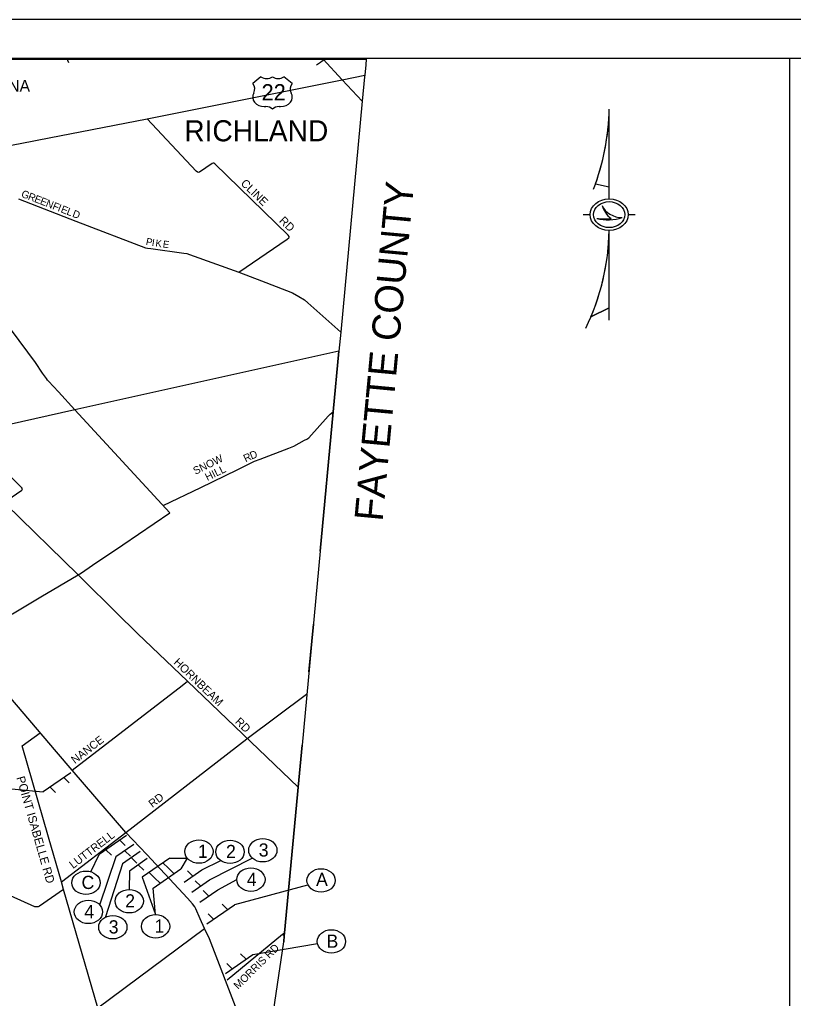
# Model space of a CAD drawing. Extents: x 0 to 784, y 0 to 440.
# Drawn here: x 266.5 to 466.8, y 186.8 to 440 of the extents above; entities that cross this region are included whole.
import ezdxf

# ---------------------------------------------------------------- set-up
doc = ezdxf.new("R2010")
doc.units = 0
for name, color, linetype in [('Default', 7, 'Continuous'), ('SH_Border', 7, 'Continuous'), ('SH_Cut_Line', 7, 'Continuous'), ('SH_Data', 7, 'Continuous'), ('SH_Text', 7, 'Continuous')]:
    doc.layers.add(name, color=color, linetype=linetype)

msp = doc.modelspace()

# ---------------------------------------------------------------- linework, layer by layer
at = {"layer": 'Default'}
for p, q in [((328.98, 425.22), (326.86, 423.46)), ((337.04, 423.46), (334.92, 425.22)), ((329.83, 417.48), (330.25, 417.48)), ((333.65, 417.48), (334.07, 417.48)), ((279.74, 245.14), (272.6, 240.17)), ((279.37, 242.5), (277.96, 243.9)), ((257.96, 241.64), (272.6, 240.17)), ((275.8, 240.02), (274.39, 241.41)), ((276.17, 242.65), (276.17, 242.65)), ((294.2, 228.93), (287.06, 223.96)), ((290.63, 226.45), (290.63, 226.45)), ((296.07, 226.57), (291.45, 223.36)), ((293.83, 226.29), (292.42, 227.69)), ((284.97, 219.55), (287.06, 223.96)), ((290.25, 223.81), (288.84, 225.2)), ((297.75, 224.77), (293.13, 221.56)), ((293.76, 224.97), (295.17, 223.57)), ((299.55, 222.94), (294.92, 219.72)), ((295.44, 223.17), (296.85, 221.77)), ((305.4, 223.05), (298.25, 218.09)), ((297.23, 221.33), (298.64, 219.94)), ((301.82, 220.57), (301.82, 220.57)), ((305.02, 220.42), (303.61, 221.81)), ((305.02, 220.43), (306.43, 219.04)), ((301.45, 217.94), (300.04, 219.33)), ((301.07, 215.31), (308.22, 220.28)), ((301.45, 217.95), (302.86, 216.55)), ((304.64, 217.8), (304.64, 217.8)), ((309.06, 216.8), (313.69, 220.01)), ((311.38, 218.4), (309.97, 219.8)), ((311.06, 214.22), (315.69, 217.44)), ((313.38, 215.83), (311.97, 217.22)), ((341.06, 216.06), (322.09, 210.99)), ((313.16, 211.65), (317.78, 214.86)), ((315.47, 213.26), (314.06, 214.65)), ((314.95, 206.03), (322.09, 210.99)), ((318.9, 211.15), (320.31, 209.75)), ((315.32, 208.66), (316.73, 207.27)), ((318.52, 208.51), (318.52, 208.51)), ((319.76, 193.2), (326.91, 198.16)), ((323.71, 198.31), (325.12, 196.92)), ((320.14, 195.83), (321.55, 194.44)), ((323.33, 195.68), (323.33, 195.68))]:
    msp.add_line(p, q, dxfattribs=at)
for points in [[(30.04, 429.76), (356.24, 429.76)], [(30.04, 429.76), (356.24, 429.76)], [(30.04, 429.76), (356.24, 429.76)], [(278.8, 429.76), (278.88, 429.49), (279.18, 428.86)], [(345.53, 429.76), (345.29, 429.54), (344.83, 429.21), (344.35, 428.89), (343.86, 428.58), (343.37, 428.24)], [(356.24, 429.76), (356.09, 428.25), (355.84, 425.6), (355.81, 425.19), (355.22, 418.92), (349.62, 359.12), (349.16, 354.22), (347.69, 338.55), (344.32, 302.45)], [(356.24, 429.76), (356.09, 428.25), (355.84, 425.6), (355.81, 425.19), (355.22, 418.92), (349.62, 359.12), (349.16, 354.22), (347.69, 338.55), (344.32, 302.45)], [(356.24, 429.76), (356.09, 428.25), (355.84, 425.6), (355.81, 425.19), (355.22, 418.92), (349.62, 359.12), (349.16, 354.22), (347.69, 338.55), (344.32, 302.45)], [(350.04, 424.44), (345.04, 429.76)], [(276.83, 409.9), (299.52, 414.29), (350.04, 424.44), (355.84, 425.6)], [(355.22, 418.92), (350.04, 424.44)], [(323.28, 374.64), (335.76, 383.21), (336.21, 383.54), (336.28, 383.74), (336.25, 383.91), (336.04, 384.24), (317.05, 402.68), (316.8, 402.87), (316.65, 402.88), (316.32, 402.79), (313.05, 400.56), (312.77, 400.46), (312.58, 400.49), (312.24, 400.74), (299.52, 414.29)], [(253.38, 405.36), (263.85, 407.39), (266.62, 407.92), (266.62, 407.92)], [(266.62, 407.92), (274.56, 409.46), (276.83, 409.9)], [(266.24, 393.59), (281.02, 387.86), (299.06, 380.98), (299.61, 380.85), (300.45, 380.74), (308.98, 379.61), (309.76, 379.47), (310.48, 379.21), (323.28, 374.64), (329.13, 372.44), (335.56, 369.94), (337.17, 369.28), (338.76, 368.39), (340.24, 367.53), (341.15, 366.72), (349.62, 359.12)], [(305.41, 312.35), (280.81, 339.02), (276.57, 343.66), (275.24, 345.07), (274.02, 346.43), (273.72, 346.74), (273.43, 347.14), (272.46, 348.48), (270.65, 351.32), (264.44, 359.64), (261.54, 363.43), (260.73, 364.63), (260.5, 365.11), (260.32, 365.8), (258.12, 377.41), (257.92, 377.84), (257.79, 378.04), (252.84, 382.75), (249.44, 385.84)], [(276.05, 250.6), (251.83, 278.94), (240.55, 292.26), (235.97, 297.77), (222.12, 314.36), (221.59, 314.93), (219.74, 316.8), (212.53, 323.9), (207.71, 328.65), (203.58, 332.82), (194.21, 342.12), (187.04, 349.36), (186.53, 349.9), (186.16, 350.28), (185.74, 350.86), (179.65, 358.52), (171.36, 368.89), (165.56, 376.17)], [(344.32, 302.45), (347.69, 338.55), (349.16, 354.22), (280.81, 339.02), (273.89, 337.48)], [(273.89, 337.48), (253.08, 332.85), (250.21, 332.22)], [(303.66, 314.26), (313.38, 318.97), (322.79, 323.53), (326.63, 325.4), (327.27, 325.72), (328.78, 326.29), (336.19, 329.08), (337.5, 329.67), (340.25, 331.16), (340.86, 331.41), (341.37, 331.79), (346.34, 337.36), (346.88, 337.88), (347.69, 338.55)], [(281.63, 296.37), (262.9, 314.64), (262.53, 314.98), (262.52, 315.04), (262.55, 315.12), (263.17, 315.58), (267.05, 318.28), (267.18, 318.42), (267.26, 318.63), (267.08, 318.87), (253.59, 332.34)], [(251.83, 278.94), (264.64, 286.29), (271.97, 290.62), (281.63, 296.37), (282.5, 296.91), (285.38, 298.87), (293.21, 304.09), (305.41, 312.35)], [(344.32, 302.45), (339.63, 252.31)], [(282.59, 295.42), (281.63, 296.37)], [(291.5, 286.63), (282.59, 295.42)], [(338.61, 241.45), (309.98, 268.81), (297.01, 281.21), (291.5, 286.63)], [(341.4, 271.25), (342.55, 283.57)], [(341.4, 271.25), (342.55, 283.57)], [(342.55, 283.57), (341.4, 271.25)], [(342.55, 283.57), (341.4, 271.25)], [(308.62, 267.76), (309.98, 268.81)], [(280.12, 245.85), (308.62, 267.76)], [(325.44, 254.01), (340.73, 265.44)], [(277.31, 216.93), (293.97, 229.72), (325.34, 253.93)], [(277.84, 214.9), (277.31, 216.93), (273.94, 228.48), (267.18, 252.09)], [(334.86, 201.37), (335, 202.95), (335.08, 203.76), (338.43, 239.52), (338.61, 241.45), (339.63, 252.31)], [(334.86, 201.37), (335, 202.95), (335.08, 203.76), (338.43, 239.52), (338.61, 241.45), (339.63, 252.31)], [(339.63, 252.31), (338.61, 241.45), (338.43, 239.52), (335.08, 203.76), (335, 202.95), (334.86, 201.37)], [(339.63, 252.31), (338.61, 241.45), (338.43, 239.52), (335.08, 203.76), (335, 202.95), (334.86, 201.37)], [(339.63, 252.31), (338.61, 241.45), (338.43, 239.52), (335.08, 203.76), (335, 202.95), (334.86, 201.37)], [(323.21, 182.43), (315.65, 202.22), (314.37, 204.87), (313.25, 207.38), (312.12, 209.93), (311.85, 210.45), (311.28, 211.22), (309.95, 212.69), (299.4, 224.01), (293.97, 229.72), (280.12, 245.85), (276.05, 250.6)], [(286.74, 184.37), (277.84, 214.9), (271.69, 210.64), (271.3, 210.44), (270.93, 210.44), (270.45, 210.49), (245.32, 221.77), (245.17, 221.81)], [(286.74, 184.37), (314.37, 204.87)], [(320.24, 191.56), (334.59, 203.36), (335.08, 203.76)], [(334.59, 203.36), (335, 202.95)], [(328.56, 159.01), (334.86, 201.37)]]:
    msp.add_lwpolyline(points, dxfattribs=at)
msp.add_lwpolyline([(31.33, 429.99), (465.77, 429.99), (465.77, 10.05), (31.33, 10.05)], close=True, dxfattribs=at)
for centre, major_axis, start_param, end_param in [((324.42, 422.05), (2.97, 0), 5.838949, 6.894067), ((330.47, 426.47), (2.12, 0), 3.936991, 5.487786), ((333.44, 426.47), (2.12, 0), 3.936991, 5.487786), ((339.48, 422.05), (-2.97, 0), 5.672304, 6.727422), ((329.8, 419.95), (2.97, 0), 2.702327, 4.723529), ((334.11, 419.95), (2.97, 0), 4.701249, 6.722451), ((330.25, 415.73), (-2.12, 0), 3.785094, 4.712389), ((333.65, 415.73), (-2.12, 0), 4.712389, 5.639684)]:
    msp.add_ellipse(centre, major_axis=major_axis, ratio=0.82844, start_param=start_param, end_param=end_param, dxfattribs=at)
for centre in [(329.46, 225.09), (312.93, 224.75), (320.97, 224.69), (326.37, 217.5), (344.54, 217.29), (283.68, 216.69), (294.87, 211.91), (284.3, 209.14), (290.63, 205.19), (301.7, 205.41), (347.22, 201.5)]:
    msp.add_ellipse(centre, major_axis=(3.66, 0), ratio=0.82844, dxfattribs=at)
at = {"layer": 'SH_Border'}
msp.add_lwpolyline([(30, 430), (670, 430), (670, 10), (30, 10)], close=True, dxfattribs=at)
at = {"layer": 'SH_Cut_Line'}
msp.add_lwpolyline([(0, 0), (680, 0), (680, 440), (0, 440)], close=True, dxfattribs=at)
at = {"layer": 'SH_Data'}
for p, q in [((419.12, 393.62), (419.12, 416.81)), ((415.62, 397.54), (419.12, 396.75)), ((412.43, 389.53), (414.18, 389.53)), ((424.06, 389.53), (425.82, 389.53)), ((419.12, 362.26), (419.12, 385.44)), ((419.12, 365.44), (414.41, 363.1))]:
    msp.add_line(p, q, dxfattribs=at)
for points in [[(415.6, 397.54), (415.62, 397.54), (419.12, 396.75), (419.12, 416.81)], [(414.41, 363.1), (419.12, 365.44), (419.12, 385.44)]]:
    msp.add_lwpolyline(points, dxfattribs=at)
for centre, major_axis, start_param, end_param in [((332.59, 417.81), (86.54, 0), 5.976274, 6.26913), ((332.59, 417.81), (86.54, 0), 5.996522, 6.26913), ((422.58, 393.4), (5.59, 0), 3.475953, 4.70141), ((424.96, 393.33), (-7.87, 0), 0.224373, 0.825788), ((418.88, 396.42), (9.93, 0), 4.406736, 5.08739), ((417.91, 398.83), (12.54, 0), 4.550557, 4.849806), ((332.59, 386.45), (86.54, 0), 5.908033, 6.26913), ((332.59, 386.45), (86.54, 0), 5.951461, 6.26913)]:
    msp.add_ellipse(centre, major_axis=major_axis, ratio=0.82844, start_param=start_param, end_param=end_param, dxfattribs=at)
for major_axis in [(4.94, 0), (4.06, 0)]:
    msp.add_ellipse((419.12, 389.53), major_axis=major_axis, ratio=0.82844, dxfattribs=at)
at = {"layer": 'SH_Text'}
for p, q in [((267.18, 252.09), (271.79, 255.45)), ((291.45, 223.36), (287.19, 210.9)), ((315.69, 217.44), (326.74, 223.05)), ((293.13, 221.56), (288.72, 207.84)), ((313.69, 220.01), (318.55, 222.46)), ((294.92, 219.72), (294.87, 214.94)), ((317.78, 214.86), (322.71, 217.5)), ((326.91, 198.16), (343.64, 200.95))]:
    msp.add_line(p, q, dxfattribs=at)
for points in [[(305.4, 223.05), (309.9, 223.05), (308.22, 220.28)], [(298.25, 218.09), (301.7, 208.44), (301.07, 215.31)]]:
    msp.add_lwpolyline(points, dxfattribs=at)

# ---------------------------------------------------------------- texts
at = {"layer": 'Default'}
for s, height, rotation, p in [('SABINA', 3.031, 0, (254.33, 421.35)), ('RICHLAND', 5.455, 0, (309.12, 408.5)), ('CLINE', 2.116, 315.7456, (323.59, 397.43)), ('FAYETTE COUNTY', 7.3165, 84.6559, (360.44, 310.02)), ('G', 1.93, 338.6698, (266.75, 394.19)), ('R', 1.93, 338.6672, (268.5, 393.51)), ('E', 1.93, 338.672, (270.13, 392.88)), ('E', 1.93, 338.672, (271.62, 392.3)), ('N', 1.93, 338.6716, (273.1, 391.72)), ('F', 1.93, 338.6664, (274.85, 391.03)), ('I', 1.93, 338.6657, (276.19, 390.51)), ('E', 1.93, 338.672, (277, 390.19)), ('L', 1.93, 338.672, (278.49, 389.61)), ('D', 1.93, 339.0625, (279.99, 389.03)), ('RD', 2.116, 315.8121, (333.54, 387.78)), ('P', 1.85, 348.7635, (299.07, 381.75)), ('I', 1.84, 351.3256, (300.63, 381.45)), ('K', 1.83, 352.5695, (301.58, 381.3)), ('E', 1.83, 352.7385, (303.49, 381.05)), ('SNOW', 1.972, 25.9583, (312, 322.21)), ('R', 1.97, 25.2309, (325.01, 325.44)), ('D', 1.94, 22.3636, (326.55, 326.17)), ('HILL', 1.972, 25.9408, (315.1, 320.61)), ('HORNBEAM', 2.114, 316.1204, (306.21, 273.51)), ('RD', 2.116, 315.8135, (322.11, 258.17)), ('NANCE', 2.071, 37.5699, (280.83, 247.35)), ('POINT ISABELLE RD', 2.1942, 285.9916, (265.64, 243.9)), ('RD', 2.071, 37.596, (300.88, 236.01)), ('LUTTRELL', 2.07, 37.4806, (280.35, 220.22)), ('MORRIS RD', 1.983, 44.6638, (323.08, 189))]:
    msp.add_text(s, height=height, rotation=rotation, dxfattribs=at).set_placement(p)
for s, height, p in [('22', 4.219, (329.13, 419.07)), ('1', 3.41, (312.65, 223.13)), ('2', 3.41, (319.94, 223.07)), ('3', 3.41, (328.41, 223.47)), ('C', 3.41, (282.53, 215.07)), ('4', 3.41, (325.33, 215.88)), ('A', 3.41, (343.24, 215.85)), ('2', 3.41, (293.84, 210.29)), ('4', 3.41, (283.27, 207.52)), ('3', 3.41, (289.58, 203.57)), ('1', 3.41, (301.42, 203.79)), ('B', 3.41, (345.95, 199.87))]:
    msp.add_text(s, height=height, dxfattribs=at).set_placement(p)

doc.saveas('drawing.dxf')
